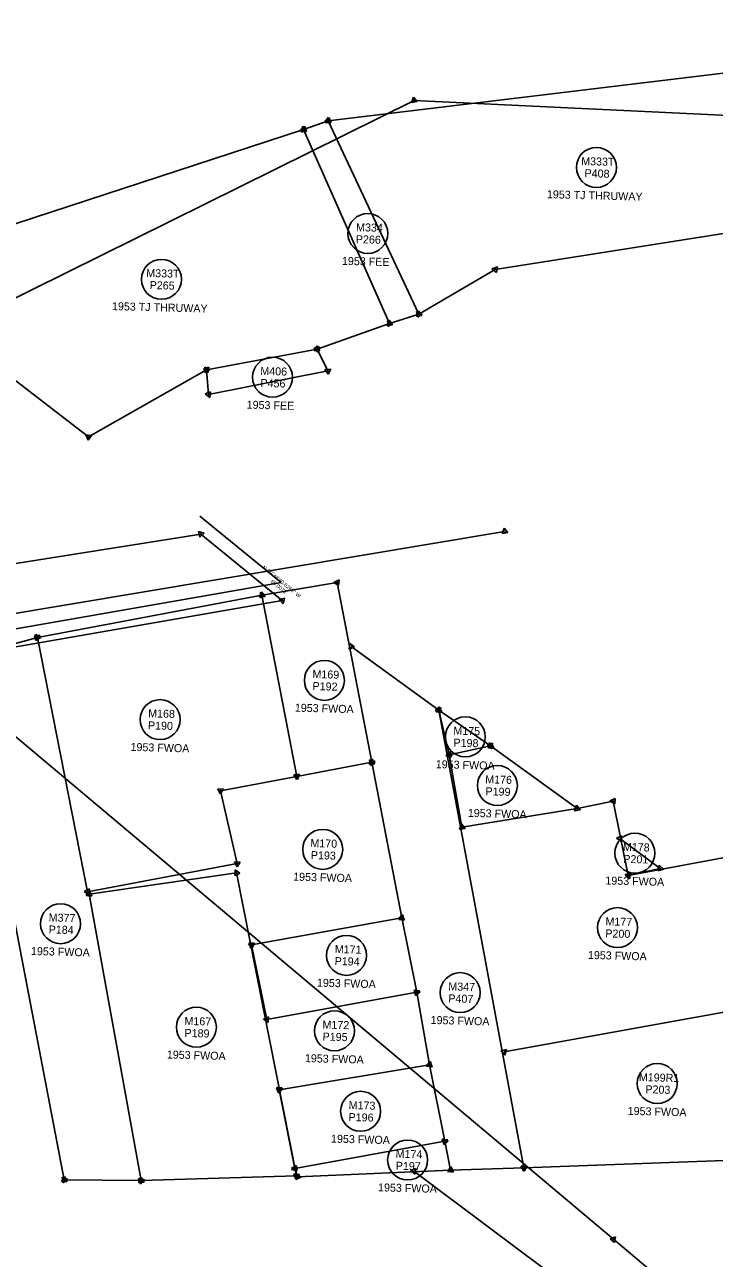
# Model space of a CAD drawing. Extents: x 325029 to 414988, y 1517527 to 1550420.
# Drawn here: x 363896 to 364349, y 1523742 to 1524551 of the extents above; entities that cross this region are included whole.
import ezdxf

# ---------------------------------------------------------------- set-up
doc = ezdxf.new("R2010")
doc.units = 0
for name, color, linetype in [('ADEFAULT', 7, 'Continuous'), ('Level 56', 7, 'Continuous'), ('MEE', 7, 'Continuous'), ('MHB', 7, 'Continuous'), ('MHBWOA', 7, 'Continuous'), ('MRBL1', 7, 'Continuous'), ('MRBL2', 7, 'Continuous'), ('XDEFAULT_P', 7, 'Continuous'), ('XDEFAULT_P_T', 7, 'Continuous')]:
    doc.layers.add(name, color=color, linetype=linetype)

msp = doc.modelspace()

# ---------------------------------------------------------------- linework, layer by layer
at = {"layer": 'ADEFAULT'}
for points in [[(364011.07, 1524215.13), (364010.09, 1524218.78)], [(364010.09, 1524218.78), (364013.74, 1524217.8)], [(364013.74, 1524217.8), (364011.07, 1524215.13)], [(364062.99, 1524174.16), (364066.64, 1524175.16)], [(364065.68, 1524171.5), (364062.99, 1524174.16)], [(364066.64, 1524175.16), (364065.68, 1524171.5)]]:
    msp.add_lwpolyline(points, dxfattribs=at)
for centre in [(364011.63, 1524217.23), (364065.1, 1524173.61)]:
    msp.add_circle(centre, 0.227, dxfattribs=at)
at = {"layer": 'Level 56'}
for centre in [(364271.32, 1524457.74), (364121.26, 1524414.41), (363985.81, 1524384.32), (364058.7, 1524320.09), (364092.76, 1524121.21), (363984.91, 1524095.44), (364185.28, 1524084.12), (364206.32, 1524052.19), (364091.65, 1524010.32), (364296.58, 1524007.83), (363919.56, 1523961.54), (364285.14, 1523958.97), (364107.27, 1523940.78), (364181.89, 1523916.31), (364008.73, 1523893.64), (364099.37, 1523891.26), (364311.24, 1523856.68), (364116.54, 1523838.45), (364147.39, 1523806.51)]:
    msp.add_circle(centre, 13.12, dxfattribs=at)
at = {"layer": 'MEE'}
msp.add_line((364151.51, 1523799.25), (364335.19, 1523661.88), dxfattribs=at)
for points in [[(364149.35, 1523799.51), (364152.82, 1523801)], [(364152.37, 1523797.24), (364149.35, 1523799.51)], [(364152.82, 1523801), (364152.37, 1523797.24)]]:
    msp.add_lwpolyline(points, dxfattribs=at)
msp.add_circle((364151.51, 1523799.25), 1.09, dxfattribs=at)
at = {"layer": 'MHB'}
for p, q in [((364095.27, 1524488.31), (364619.09, 1524551.41)), ((364079.15, 1524482.56), (364095.27, 1524488.31)), ((364154.7, 1524361.52), (364095.27, 1524488.31)), ((363795.7, 1524390.2), (364079.15, 1524482.56)), ((364079.15, 1524482.56), (364135.45, 1524355.33)), ((364776.9, 1524480.78), (364204.91, 1524390.84)), ((363937.94, 1524280.97), (363795.7, 1524390.2)), ((364204.91, 1524390.84), (364154.7, 1524361.52)), ((364154.7, 1524361.52), (364135.45, 1524355.33)), ((364135.45, 1524355.33), (364087.98, 1524338.52)), ((364087.98, 1524338.52), (364015.48, 1524324.94)), ((364095.08, 1524324.19), (364087.98, 1524338.52)), ((364015.48, 1524324.94), (363937.94, 1524280.97)), ((364015.48, 1524324.94), (364016.75, 1524308.84)), ((364016.75, 1524308.84), (364095.08, 1524324.19))]:
    msp.add_line(p, q, dxfattribs=at)
for points in [[(364093.11, 1524488.03), (364096.11, 1524490.32)], [(364096.6, 1524486.58), (364093.11, 1524488.03)], [(364093.3, 1524487.39), (364095.46, 1524490.49)], [(364097.06, 1524487.07), (364093.3, 1524487.39)], [(364093.53, 1524487), (364095.01, 1524490.48)], [(364097.28, 1524487.45), (364093.53, 1524487)], [(364095.01, 1524490.48), (364097.28, 1524487.45)], [(364095.46, 1524490.49), (364097.06, 1524487.07)], [(364096.11, 1524490.32), (364096.6, 1524486.58)], [(364076.98, 1524482.33), (364080.04, 1524484.55)], [(364080.43, 1524480.79), (364076.98, 1524482.33)], [(364077.16, 1524481.68), (364079.39, 1524484.73)], [(364080.91, 1524481.28), (364077.16, 1524481.68)], [(364077.74, 1524480.9), (364078.42, 1524484.61)], [(364081.3, 1524482.17), (364077.74, 1524480.9)], [(364078.42, 1524484.61), (364081.3, 1524482.17)], [(364079.39, 1524484.73), (364080.91, 1524481.28)], [(364080.04, 1524484.55), (364080.43, 1524480.79)], [(364202.76, 1524391.24), (364206.32, 1524392.5)], [(364205.64, 1524388.79), (364202.76, 1524391.24)], [(364206.32, 1524392.5), (364205.64, 1524388.79)], [(364133.7, 1524354.03), (364135.19, 1524357.5)], [(364135.19, 1524357.5), (364137.45, 1524354.47)], [(364152.95, 1524360.22), (364154.46, 1524363.69)], [(364156.7, 1524360.65), (364152.95, 1524360.22)], [(364154.06, 1524359.44), (364153.22, 1524363.13)], [(364153.22, 1524363.13), (364156.83, 1524362)], [(364156.83, 1524362), (364154.06, 1524359.44)], [(364154.46, 1524363.69), (364156.7, 1524360.65)], [(364137.45, 1524354.47), (364133.7, 1524354.03)], [(364134.56, 1524353.35), (364134.17, 1524357.1)], [(364134.17, 1524357.1), (364137.62, 1524355.56)], [(364137.62, 1524355.56), (364134.56, 1524353.35)], [(364085.87, 1524339.09), (364089.52, 1524340.07)], [(364088.54, 1524336.42), (364085.87, 1524339.09)], [(364086.03, 1524337.56), (364088.12, 1524340.7)], [(364089.8, 1524337.32), (364086.03, 1524337.56)], [(364088.12, 1524340.7), (364089.8, 1524337.32)], [(364089.52, 1524340.07), (364088.54, 1524336.42)], [(364013.33, 1524325.32), (364016.87, 1524326.62)], [(364016.22, 1524322.9), (364013.33, 1524325.32)], [(364014.24, 1524326.74), (364017.65, 1524325.12)], [(364014.53, 1524322.97), (364014.24, 1524326.74)], [(364017.65, 1524325.12), (364014.53, 1524322.97)], [(364016.87, 1524326.62), (364016.22, 1524322.9)], [(364093.12, 1524325.15), (364096.89, 1524325.4)], [(364095.22, 1524322.01), (364093.12, 1524325.15)], [(364096.89, 1524325.4), (364095.22, 1524322.01)], [(364014.59, 1524309.11), (364018.07, 1524310.57)], [(364017.6, 1524306.83), (364014.59, 1524309.11)], [(364018.07, 1524310.57), (364017.6, 1524306.83)], [(363937.78, 1524278.8), (363936.13, 1524282.2)], [(363936.13, 1524282.2), (363939.9, 1524281.93)], [(363939.9, 1524281.93), (363937.78, 1524278.8)]]:
    msp.add_lwpolyline(points, dxfattribs=at)
for centre, radius in [((364095.27, 1524488.32), 1.09), ((364095.27, 1524488.31), 1.09), ((364095.27, 1524488.31), 0.227), ((364079.15, 1524482.57), 1.09), ((364079.15, 1524482.56), 1.09), ((364079.15, 1524482.56), 0.227), ((364204.91, 1524390.84), 0.227), ((364154.7, 1524361.52), 0.227), ((364154.7, 1524361.52), 0.227), ((364135.45, 1524355.33), 0.227), ((364135.45, 1524355.33), 0.227), ((364087.98, 1524338.53), 1.09), ((364087.98, 1524338.52), 0.227), ((364015.48, 1524324.94), 1.09), ((364015.48, 1524324.94), 0.227), ((364095.08, 1524324.19), 0.227), ((364016.75, 1524308.84), 0.227), ((363937.94, 1524280.97), 0.227)]:
    msp.add_circle(centre, radius, dxfattribs=at)
at = {"layer": 'MHBWOA'}
for p, q in [((364011.63, 1524217.23), (363660.19, 1524161.2)), ((364065.1, 1524173.61), (364011.63, 1524217.23)), ((364051.8, 1524177.07), (364101.12, 1524185.31)), ((364101.12, 1524185.31), (364123.85, 1524067.45)), ((363722.48, 1524114.08), (364065.1, 1524173.61)), ((364051.8, 1524177.07), (363904.35, 1524149.4)), ((364074.7, 1524058.22), (364051.8, 1524177.07)), ((363904.35, 1524149.4), (363856.11, 1524136.32)), ((363904.35, 1524149.4), (363937.29, 1523982.55)), ((364167.87, 1524101.61), (364110.3, 1524143.46)), ((363856.11, 1524136.32), (363922.05, 1523793.54)), ((364167.87, 1524101.61), (364201.83, 1524078.29)), ((364174.67, 1524072.39), (364167.87, 1524101.61)), ((364223.73, 1523801.26), (364167.87, 1524101.61)), ((364201.83, 1524078.29), (364174.67, 1524072.39)), ((364201.83, 1524078.29), (364258.64, 1524037.09)), ((364123.85, 1524067.45), (364074.7, 1524058.22)), ((364123.85, 1524067.45), (364143.49, 1523965.35)), ((364183.05, 1524024.85), (364174.67, 1524072.39)), ((364024.56, 1524048.83), (364074.7, 1524058.22)), ((364035.59, 1524001), (364024.56, 1524048.83)), ((364258.64, 1524037.09), (364282.35, 1524041.98)), ((364282.35, 1524041.98), (364292.26, 1523993.16)), ((364183.05, 1524024.85), (364258.64, 1524037.09)), ((364286.6, 1524017.51), (364313.15, 1523997.81)), ((364292.26, 1523993.16), (364390.03, 1524011.58)), ((363937.29, 1523982.55), (364035.59, 1524001)), ((364035.17, 1523994.99), (363938.44, 1523980.92)), ((364074.42, 1523796.11), (364035.17, 1523994.99)), ((364313.15, 1523997.81), (364292.26, 1523993.16)), ((363938.44, 1523980.92), (363972.49, 1523792.95)), ((364143.49, 1523965.35), (364044.96, 1523947.58)), ((364153.41, 1523916.53), (364143.49, 1523965.35)), ((364044.96, 1523947.58), (364054.87, 1523898.75)), ((364054.87, 1523898.75), (364153.41, 1523916.53)), ((364153.41, 1523916.53), (364161.79, 1523868.99)), ((364407.8, 1523913.04), (364210.73, 1523877.49)), ((364161.79, 1523868.99), (364063.13, 1523852.62)), ((364171.82, 1523818.76), (364161.79, 1523868.99)), ((364063.13, 1523852.62), (364073.29, 1523800.98)), ((364073.29, 1523800.98), (364171.82, 1523818.76)), ((364171.82, 1523818.76), (364175.59, 1523799.92)), ((364427.48, 1523808.99), (364223.73, 1523801.26)), ((364075.19, 1523795.47), (364073.29, 1523800.98)), ((364175.59, 1523799.92), (364075.19, 1523795.47)), ((364175.59, 1523799.92), (364223.73, 1523801.26)), ((363922.05, 1523793.54), (363972.49, 1523792.95)), ((363972.49, 1523792.95), (364074.42, 1523796.11))]:
    msp.add_line(p, q, dxfattribs=at)
for points in [[(364050.12, 1524175.68), (364051.44, 1524179.22)], [(364051.44, 1524179.22), (364053.84, 1524176.31)], [(364098.94, 1524185.49), (364102.36, 1524187.1)], [(364102.04, 1524183.34), (364098.94, 1524185.49)], [(364102.36, 1524187.1), (364102.04, 1524183.34)], [(364053.84, 1524176.31), (364050.12, 1524175.68)], [(364050.58, 1524175.27), (364050.85, 1524179.04)], [(364053.98, 1524176.92), (364050.58, 1524175.27)], [(364050.85, 1524179.04), (364053.98, 1524176.92)], [(363902.29, 1524150.13), (363906, 1524150.82)], [(363904.75, 1524147.26), (363902.29, 1524150.13)], [(363902.91, 1524151.04), (363906.48, 1524149.82)], [(363903.64, 1524147.34), (363902.91, 1524151.04)], [(363903.19, 1524147.55), (363903.32, 1524151.33)], [(363906.53, 1524149.33), (363903.19, 1524147.55)], [(363903.32, 1524151.33), (363906.53, 1524149.33)], [(363906.48, 1524149.82), (363903.64, 1524147.34)], [(363906, 1524150.82), (363904.75, 1524147.26)], [(364109.02, 1524141.7), (364109.41, 1524145.46)], [(364112.47, 1524143.23), (364109.02, 1524141.7)], [(364109.41, 1524145.46), (364112.47, 1524143.23)], [(364165.7, 1524101.78), (364169.1, 1524103.4)], [(364168.81, 1524099.64), (364165.7, 1524101.78)], [(364165.75, 1524101.12), (364168.51, 1524103.7)], [(364169.37, 1524100.02), (364165.75, 1524101.12)], [(364166.03, 1524100.45), (364167.79, 1524103.79)], [(364169.81, 1524100.6), (364166.03, 1524100.45)], [(364167.79, 1524103.79), (364169.81, 1524100.6)], [(364168.51, 1524103.7), (364169.37, 1524100.02)], [(364169.1, 1524103.4), (364168.81, 1524099.64)], [(364172.52, 1524072.01), (364175.41, 1524074.44)], [(364173.5, 1524070.55), (364173.65, 1524074.32)], [(364173.65, 1524074.32), (364176.85, 1524072.3)], [(364175.41, 1524074.44), (364176.07, 1524070.72)], [(364199.66, 1524078.52), (364203.11, 1524080.06)], [(364202.72, 1524076.3), (364199.66, 1524078.52)], [(364200.4, 1524076.65), (364201.12, 1524080.36)], [(364203.97, 1524077.87), (364200.4, 1524076.65)], [(364201.12, 1524080.36), (364203.97, 1524077.87)], [(364203.11, 1524080.06), (364202.72, 1524076.3)], [(364121.88, 1524066.5), (364124.01, 1524069.62)], [(364125.65, 1524066.22), (364121.88, 1524066.5)], [(364122.42, 1524069.1), (364125.99, 1524067.86)], [(364123.13, 1524065.39), (364122.42, 1524069.1)], [(364125.99, 1524067.86), (364123.13, 1524065.39)], [(364124.01, 1524069.62), (364125.65, 1524066.22)], [(364176.07, 1524070.72), (364172.52, 1524072.01)], [(364176.85, 1524072.3), (364173.5, 1524070.55)], [(364072.64, 1524058.95), (364076.35, 1524059.65)], [(364075.1, 1524056.08), (364072.64, 1524058.95)], [(364074.54, 1524056.05), (364072.9, 1524059.45)], [(364072.9, 1524059.45), (364076.66, 1524059.17)], [(364076.66, 1524059.17), (364074.54, 1524056.05)], [(364076.35, 1524059.65), (364075.1, 1524056.08)], [(364024.44, 1524046.65), (364022.74, 1524050.03)], [(364022.74, 1524050.03), (364026.51, 1524049.81)], [(364026.51, 1524049.81), (364024.44, 1524046.65)], [(364280.17, 1524042.11), (364283.55, 1524043.8)], [(364283.32, 1524040.03), (364280.17, 1524042.11)], [(364283.55, 1524043.8), (364283.32, 1524040.03)], [(364256.98, 1524035.67), (364258.25, 1524039.23)], [(364260.7, 1524036.35), (364256.98, 1524035.67)], [(364257.14, 1524035.5), (364258.01, 1524039.18)], [(364260.76, 1524036.58), (364257.14, 1524035.5)], [(364258.01, 1524039.18), (364260.76, 1524036.58)], [(364258.25, 1524039.23), (364260.7, 1524036.35)], [(364181.36, 1524023.47), (364182.7, 1524027)], [(364181.79, 1524023.08), (364182.14, 1524026.84)], [(364182.14, 1524026.84), (364185.22, 1524024.65)], [(364182.7, 1524027), (364185.09, 1524024.07)], [(364185.09, 1524024.07), (364181.36, 1524023.47)], [(364185.22, 1524024.65), (364181.79, 1524023.08)], [(364284.43, 1524017.76), (364287.9, 1524019.26)], [(364287.46, 1524015.51), (364284.43, 1524017.76)], [(364287.9, 1524019.26), (364287.46, 1524015.51)], [(364035.47, 1523998.82), (364033.77, 1524002.19)], [(364033.77, 1524002.19), (364037.54, 1524001.98)], [(364037.54, 1524001.98), (364035.47, 1523998.82)], [(364033.91, 1523993.21), (364034.26, 1523996.97)], [(364037.34, 1523994.79), (364033.91, 1523993.21)], [(364034.26, 1523996.97), (364037.34, 1523994.79)], [(364290.08, 1523993.31), (364293.48, 1523994.97)], [(364293.22, 1523991.2), (364290.08, 1523993.31)], [(364290.18, 1523993.82), (364293.87, 1523994.64)], [(364292.73, 1523991.03), (364290.18, 1523993.82)], [(364293.87, 1523994.64), (364292.73, 1523991.03)], [(364293.48, 1523994.97), (364293.22, 1523991.2)], [(364311.69, 1523996.19), (364312.47, 1523999.89)], [(364315.28, 1523997.36), (364311.69, 1523996.19)], [(364312.47, 1523999.89), (364315.28, 1523997.36)], [(363935.11, 1523982.7), (363938.51, 1523984.35)], [(363938.24, 1523980.58), (363935.11, 1523982.7)], [(363936.45, 1523980.03), (363938.66, 1523983.09)], [(363940.21, 1523979.65), (363936.45, 1523980.03)], [(363938.51, 1523984.35), (363938.24, 1523980.58)], [(363938.66, 1523983.09), (363940.21, 1523979.65)], [(364141.36, 1523964.92), (364144.19, 1523967.42)], [(364144.94, 1523963.72), (364141.36, 1523964.92)], [(364141.52, 1523964.41), (364143.66, 1523967.53)], [(364145.29, 1523964.12), (364141.52, 1523964.41)], [(364143.66, 1523967.53), (364145.29, 1523964.12)], [(364144.19, 1523967.42), (364144.94, 1523963.72)], [(364042.91, 1523948.32), (364046.62, 1523948.99)], [(364045.35, 1523945.43), (364042.91, 1523948.32)], [(364043.51, 1523949.21), (364047.09, 1523948.01)], [(364044.26, 1523945.51), (364043.51, 1523949.21)], [(364047.09, 1523948.01), (364044.26, 1523945.51)], [(364046.62, 1523948.99), (364045.35, 1523945.43)], [(364153.25, 1523914.35), (364151.6, 1523917.75)], [(364151.6, 1523917.75), (364155.37, 1523917.48)], [(364152, 1523918.2), (364155.55, 1523916.9)], [(364152.66, 1523914.48), (364152, 1523918.2)], [(364155.55, 1523916.9), (364152.66, 1523914.48)], [(364155.37, 1523917.48), (364153.25, 1523914.35)], [(364052.69, 1523898.91), (364056.09, 1523900.55)], [(364055.82, 1523896.79), (364052.69, 1523898.91)], [(364056.09, 1523900.55), (364055.82, 1523896.79)], [(364208.68, 1523878.23), (364212.4, 1523878.91)], [(364211.12, 1523875.35), (364208.68, 1523878.23)], [(364212.4, 1523878.91), (364211.12, 1523875.35)], [(364159.65, 1523868.56), (364162.49, 1523871.06)], [(364163.23, 1523867.35), (364159.65, 1523868.56)], [(364159.8, 1523868.08), (364161.99, 1523871.16)], [(364163.57, 1523867.73), (364159.8, 1523868.08)], [(364161.99, 1523871.16), (364163.57, 1523867.73)], [(364162.49, 1523871.06), (364163.23, 1523867.35)], [(364061.09, 1523853.39), (364064.82, 1523854.01)], [(364063.49, 1523850.48), (364061.09, 1523853.39)], [(364061.69, 1523854.27), (364065.27, 1523853.04)], [(364062.42, 1523850.56), (364061.69, 1523854.27)], [(364065.27, 1523853.04), (364062.42, 1523850.56)], [(364064.82, 1523854.01), (364063.49, 1523850.48)], [(364171.67, 1523816.58), (364170.02, 1523819.98)], [(364170.02, 1523819.98), (364173.79, 1523819.7)], [(364170.38, 1523820.4), (364173.96, 1523819.18)], [(364171.12, 1523816.69), (364170.38, 1523820.4)], [(364173.96, 1523819.18), (364171.12, 1523816.69)], [(364173.79, 1523819.7), (364171.67, 1523816.58)], [(364071.11, 1523801.15), (364074.52, 1523802.78)], [(364074.23, 1523799.01), (364071.11, 1523801.15)], [(364071.23, 1523800.27), (364073.71, 1523803.13)], [(364074.94, 1523799.55), (364071.23, 1523800.27)], [(364073.71, 1523803.13), (364074.94, 1523799.55)], [(364074.52, 1523802.78), (364074.23, 1523799.01)], [(364173.56, 1523799.11), (364175.89, 1523802.08)], [(364177.3, 1523798.58), (364173.56, 1523799.11)], [(364173.73, 1523798.77), (364175.53, 1523802.1)], [(364177.51, 1523798.88), (364173.73, 1523798.77)], [(364175.53, 1523802.1), (364177.51, 1523798.88)], [(364175.89, 1523802.08), (364177.3, 1523798.58)], [(364221.81, 1523802.28), (364225.58, 1523802.42)], [(364223.82, 1523799.08), (364221.81, 1523802.28)], [(364223.4, 1523799.1), (364222.04, 1523802.63)], [(364222.04, 1523802.63), (364225.77, 1523802.04)], [(364225.77, 1523802.04), (364223.4, 1523799.1)], [(364225.58, 1523802.42), (364223.82, 1523799.08)], [(363920.14, 1523792.47), (363922.07, 1523795.72)], [(363923.92, 1523792.43), (363920.14, 1523792.47)], [(363920.61, 1523795.19), (363924.18, 1523793.95)], [(363921.33, 1523791.48), (363920.61, 1523795.19)], [(363924.18, 1523793.95), (363921.33, 1523791.48)], [(363922.07, 1523795.72), (363923.92, 1523792.43)], [(363970.64, 1523791.8), (363972.42, 1523795.13)], [(363974.41, 1523791.91), (363970.64, 1523791.8)], [(363972.12, 1523790.8), (363970.82, 1523794.35)], [(363970.82, 1523794.35), (363974.54, 1523793.7)], [(363971.08, 1523794.61), (363974.63, 1523793.34)], [(363971.75, 1523790.9), (363971.08, 1523794.61)], [(363974.63, 1523793.34), (363971.75, 1523790.9)], [(363974.54, 1523793.7), (363972.12, 1523790.8)], [(363972.42, 1523795.13), (363974.41, 1523791.91)], [(364074.1, 1523793.95), (364072.72, 1523797.47)], [(364072.72, 1523797.47), (364076.45, 1523796.91)], [(364073.96, 1523793.67), (364074.24, 1523797.44)], [(364077.36, 1523795.31), (364073.96, 1523793.67)], [(364076.45, 1523796.91), (364074.1, 1523793.95)], [(364074.24, 1523797.44), (364077.36, 1523795.31)]]:
    msp.add_lwpolyline(points, dxfattribs=at)
for centre, radius in [((364101.12, 1524185.31), 0.227), ((364051.8, 1524177.07), 1.09), ((364051.8, 1524177.07), 0.227), ((363904.35, 1524149.4), 1.09), ((363904.34, 1524149.4), 1.09), ((363904.35, 1524149.4), 0.227), ((364110.3, 1524143.46), 1.09), ((364167.87, 1524101.61), 1.09), ((364167.87, 1524101.61), 1.09), ((364167.87, 1524101.61), 0.227), ((364201.84, 1524078.29), 1.09), ((364201.83, 1524078.29), 0.227), ((364123.85, 1524067.44), 1.09), ((364123.85, 1524067.45), 0.227), ((364174.66, 1524072.39), 1.09), ((364174.67, 1524072.39), 0.227), ((364074.69, 1524058.22), 1.09), ((364074.7, 1524058.22), 0.227), ((364024.56, 1524048.83), 0.227), ((364282.35, 1524041.98), 0.227), ((364258.64, 1524037.09), 0.227), ((364258.64, 1524037.09), 0.227), ((364183.05, 1524024.85), 1.09), ((364183.05, 1524024.85), 0.227), ((364286.6, 1524017.51), 1.09), ((364035.59, 1524001), 0.227), ((364035.17, 1523994.99), 0.227), ((364292.26, 1523993.16), 1.09), ((364292.26, 1523993.16), 0.227), ((364313.15, 1523997.81), 0.227), ((363937.29, 1523982.55), 0.227), ((363938.44, 1523980.92), 0.227), ((364143.49, 1523965.35), 1.09), ((364143.49, 1523965.35), 0.227), ((364044.96, 1523947.58), 1.09), ((364044.96, 1523947.57), 1.09), ((364153.41, 1523916.52), 1.09), ((364153.41, 1523916.53), 0.227), ((364054.87, 1523898.75), 0.227), ((364210.73, 1523877.49), 1.09), ((364161.79, 1523868.99), 1.09), ((364161.79, 1523868.99), 0.227), ((364063.13, 1523852.62), 1.09), ((364063.13, 1523852.62), 1.09), ((364171.82, 1523818.75), 1.09), ((364171.82, 1523818.76), 0.227), ((364073.29, 1523800.99), 1.09), ((364073.29, 1523800.98), 0.227), ((364175.59, 1523799.92), 1.09), ((364175.59, 1523799.92), 0.227), ((364223.73, 1523801.26), 1.09), ((364223.73, 1523801.26), 0.227), ((363922.05, 1523793.54), 1.09), ((363922.05, 1523793.54), 1.09), ((363972.49, 1523792.95), 1.09), ((363972.49, 1523792.95), 1.09), ((363972.49, 1523792.95), 0.227), ((364074.42, 1523796.11), 0.227), ((364075.19, 1523795.47), 0.227)]:
    msp.add_circle(centre, radius, dxfattribs=at)
at = {"layer": 'MRBL1'}
for p, q in [((363674.46, 1524265.46), (364151.59, 1524501.69)), ((364151.59, 1524501.69), (365471.78, 1524438.52)), ((363809.67, 1524151.83), (364211.09, 1524218.89))]:
    msp.add_line(p, q, dxfattribs=at)
for points in [[(364149.97, 1524500.24), (364151.15, 1524503.83)], [(364151.15, 1524503.83), (364153.67, 1524501.01)], [(364153.67, 1524501.01), (364149.97, 1524500.24)], [(364209.4, 1524217.5), (364210.73, 1524221.04)], [(364210.73, 1524221.04), (364213.13, 1524218.12)], [(364213.13, 1524218.12), (364209.4, 1524217.5)]]:
    msp.add_lwpolyline(points, dxfattribs=at)
for centre, radius in [((364151.59, 1524501.69), 0.227), ((364211.09, 1524218.89), 1.09)]:
    msp.add_circle(centre, radius, dxfattribs=at)
at = {"layer": 'MRBL2'}
for p, q in [((363809.67, 1524151.83), (364282.48, 1523754.5)), ((364282.48, 1523754.5), (364791.76, 1523326.52))]:
    msp.add_line(p, q, dxfattribs=at)
for points in [[(364280.33, 1523754.88), (364283.88, 1523756.17)], [(364283.22, 1523752.45), (364280.33, 1523754.88)], [(364283.88, 1523756.17), (364283.22, 1523752.45)]]:
    msp.add_lwpolyline(points, dxfattribs=at)
msp.add_circle((364282.48, 1523754.5), 0.227, dxfattribs=at)
at = {"layer": 'XDEFAULT_P'}
for p, q in [((364064.43, 1524185.43), (364010.94, 1524229.04)), ((363721.83, 1524125.76), (364064.43, 1524185.43))]:
    msp.add_line(p, q, dxfattribs=at)

# ---------------------------------------------------------------- texts
at = {"layer": 'Level 56'}
for s, height, p in [('M333T', 5.249, (364261.28, 1524459.31)), ('P408', 5.249, (364263.47, 1524451.38)), ('1953 TJ THRUWAY', 5.2493, (364238.77, 1524437.57)), ('M334', 5.249, (364113.5, 1524415.93)), ('P266', 5.249, (364113.35, 1524408.06)), ('1953 FEE', 5.249, (364104.23, 1524393.84)), ('M333T', 5.249, (363975.77, 1524385.89)), ('P265', 5.249, (363978.02, 1524377.96)), ('1953 TJ THRUWAY', 5.2493, (363953.27, 1524364.15)), ('M406', 5.249, (364050.65, 1524321.61)), ('P456', 5.249, (364050.75, 1524313.73)), ('1953 FEE', 5.249, (364041.67, 1524299.51)), ('M169', 5.249, (364084.87, 1524122.73)), ('P192', 5.249, (364084.92, 1524114.86)), ('M168', 5.249, (363977.03, 1524096.97)), ('1953 FWOA', 5.249, (364073.31, 1524100.7)), ('P190', 5.249, (363976.87, 1524089.09)), ('M175', 5.249, (364177.35, 1524085.64)), ('P198', 5.249, (364177.43, 1524077.76)), ('1953 FWOA', 5.249, (363965.45, 1524074.94)), ('1953 FWOA', 5.249, (364165.82, 1524063.61)), ('M176', 5.249, (364198.27, 1524053.71)), ('P199', 5.249, (364198.46, 1524045.83)), ('1953 FWOA', 5.249, (364186.87, 1524031.68)), ('M170', 5.249, (364083.52, 1524011.85)), ('P193', 5.249, (364083.82, 1524003.97)), ('M178', 5.249, (364288.65, 1524009.35)), ('P201', 5.249, (364288.92, 1524001.46)), ('1953 FWOA', 5.249, (364072.19, 1523989.82)), ('1953 FWOA', 5.249, (364277.13, 1523987.32)), ('M377', 5.249, (363911.72, 1523963.06)), ('M177', 5.249, (364277.21, 1523960.49)), ('P184', 5.249, (363911.72, 1523955.18)), ('P200', 5.249, (364277.11, 1523952.62)), ('1953 FWOA', 5.249, (363900.1, 1523941.03)), ('M171', 5.249, (364099.52, 1523942.3)), ('P194', 5.249, (364099.43, 1523934.42)), ('1953 FWOA', 5.249, (364265.69, 1523938.46)), ('1953 FWOA', 5.249, (364087.82, 1523920.27)), ('M347', 5.249, (364174.05, 1523917.83)), ('P407', 5.249, (364174.05, 1523909.95)), ('M167', 5.249, (364000.85, 1523895.16)), ('M172', 5.249, (364091.44, 1523892.78)), ('1953 FWOA', 5.249, (364162.44, 1523895.8)), ('P189', 5.249, (364000.87, 1523887.28)), ('P195', 5.249, (364091.53, 1523884.9)), ('1953 FWOA', 5.249, (363989.28, 1523873.13)), ('1953 FWOA', 5.249, (364079.92, 1523870.75)), ('M199R1', 5.249, (364299.13, 1523858.31)), ('P203', 5.249, (364303.41, 1523850.32)), ('M173', 5.249, (364108.63, 1523839.97)), ('1953 FWOA', 5.249, (364291.78, 1523836.17)), ('P196', 5.249, (364108.57, 1523832.1)), ('1953 FWOA', 5.249, (364097.08, 1523817.94)), ('M174', 5.249, (364139.46, 1523808.03)), ('P197', 5.249, (364139.54, 1523800.15)), ('1953 FWOA', 5.249, (364127.93, 1523786))]:
    msp.add_text(s, height=height, rotation=358.49067, dxfattribs=at).set_placement(p)
at = {"layer": 'XDEFAULT_P_T'}
for s, height, p in [('N 50%%d48\'40.6266" W', 2.5008, (364051.9, 1524194.84)), ('69.0072', 2.501, (364057.23, 1524185.65))]:
    msp.add_text(s, height=height, rotation=320.81129, dxfattribs=at).set_placement(p)

doc.saveas('drawing.dxf')
